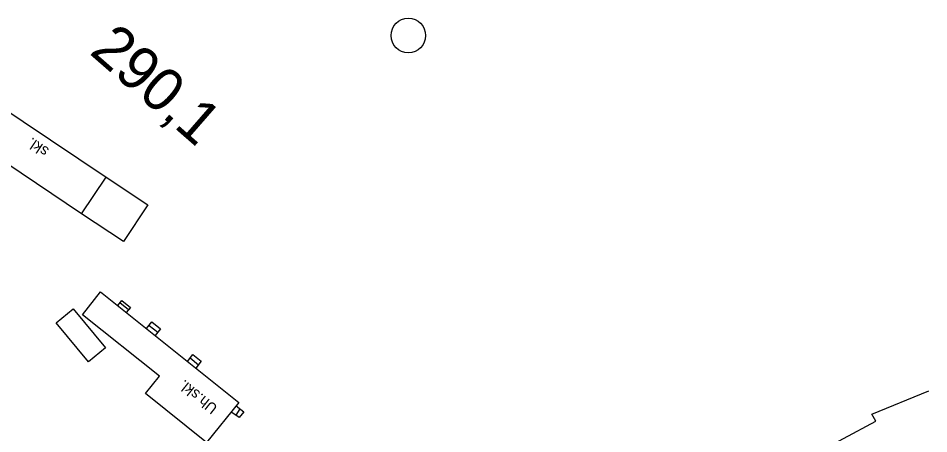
# Model space of a CAD drawing. Extents: x -496570 to -495506, y -1089156 to -1088046.
# Drawn here: x -496321.4 to -496194.6, y -1088285 to -1088227.1 of the extents above; entities that cross this region are included whole.
import ezdxf

# ---------------------------------------------------------------- set-up
doc = ezdxf.new("R2010")
doc.units = 0
for name, color, linetype in [('10', 7, 'Continuous'), ('11', 7, 'Continuous'), ('39', 7, 'Continuous')]:
    doc.layers.add(name, color=color, linetype=linetype)

msp = doc.modelspace()

# ---------------------------------------------------------------- linework, layer by layer
at = {"layer": '10'}
msp.add_lwpolyline([(-496316.13, -1088269.522), (-496313.788, -1088267.568), (-496309.268, -1088273.004), (-496311.621, -1088274.929), (-496316.13, -1088269.522)], dxfattribs=at)
at = {"layer": '39'}
for p, q in [((-496307.572, -1088267.101), (-496307.006, -1088266.394)), ((-496306.08, -1088267.692), (-496307.278, -1088266.733)), ((-496307.006, -1088266.394), (-496305.804, -1088267.347)), ((-496305.804, -1088267.347), (-496306.374, -1088268.059)), ((-496303.569, -1088270.304), (-496302.8, -1088269.342)), ((-496302.8, -1088269.342), (-496301.602, -1088270.326)), ((-496303.205, -1088269.848), (-496301.994, -1088270.816)), ((-496301.602, -1088270.326), (-496302.359, -1088271.272)), ((-496297.869, -1088274.865), (-496297.123, -1088273.932)), ((-496297.491, -1088274.392), (-496296.318, -1088275.331)), ((-496297.123, -1088273.932), (-496295.941, -1088274.86)), ((-496295.941, -1088274.86), (-496296.696, -1088275.803)), ((-496291.062, -1088281.055), (-496290.006, -1088281.913)), ((-496291.398, -1088282.187), (-496291.779, -1088281.936)), ((-496290.637, -1088282.689), (-496291.398, -1088282.187)), ((-496290.549, -1088281.472), (-496291.135, -1088282.36)), ((-496290.006, -1088281.913), (-496290.637, -1088282.689))]:
    msp.add_line(p, q, dxfattribs=at)
for points in [[(-496306.766, -1088258.19), (-496312.619, -1088254.307), (-496335.736, -1088238.781), (-496332.365, -1088233.683), (-496309.194, -1088249.189), (-496303.385, -1088253.076), (-496306.766, -1088258.19)], [(-496312.619, -1088254.307), (-496309.194, -1088249.189)], [(-496312.479, -1088268.372), (-496309.984, -1088265.171), (-496290.696, -1088280.604), (-496295.221, -1088286.171), (-496303.69, -1088279.36), (-496301.745, -1088276.917), (-496312.479, -1088268.372)], [(-496219.985, -1088292.853), (-496201.96, -1088283.211), (-496202.493, -1088282.215), (-496194.574, -1088278.952)]]:
    msp.add_lwpolyline(points, dxfattribs=at)
msp.add_circle((-496267.084, -1088229.481), 2.412, dxfattribs=at)

# ---------------------------------------------------------------- texts
at = {"layer": '11'}
msp.add_text('290,1', height=6, rotation=318.94379, dxfattribs=at).set_placement((-496311.665, -1088231.924))
at = {"layer": '39'}
for s, rotation, p in [('skl.', 146.11363, (-496317.037, -1088245.275)), ('Uh.skl.', 141.19281, (-496293.535, -1088281.172))]:
    msp.add_text(s, height=1.5, rotation=rotation, dxfattribs=at).set_placement(p)

doc.saveas('drawing.dxf')
